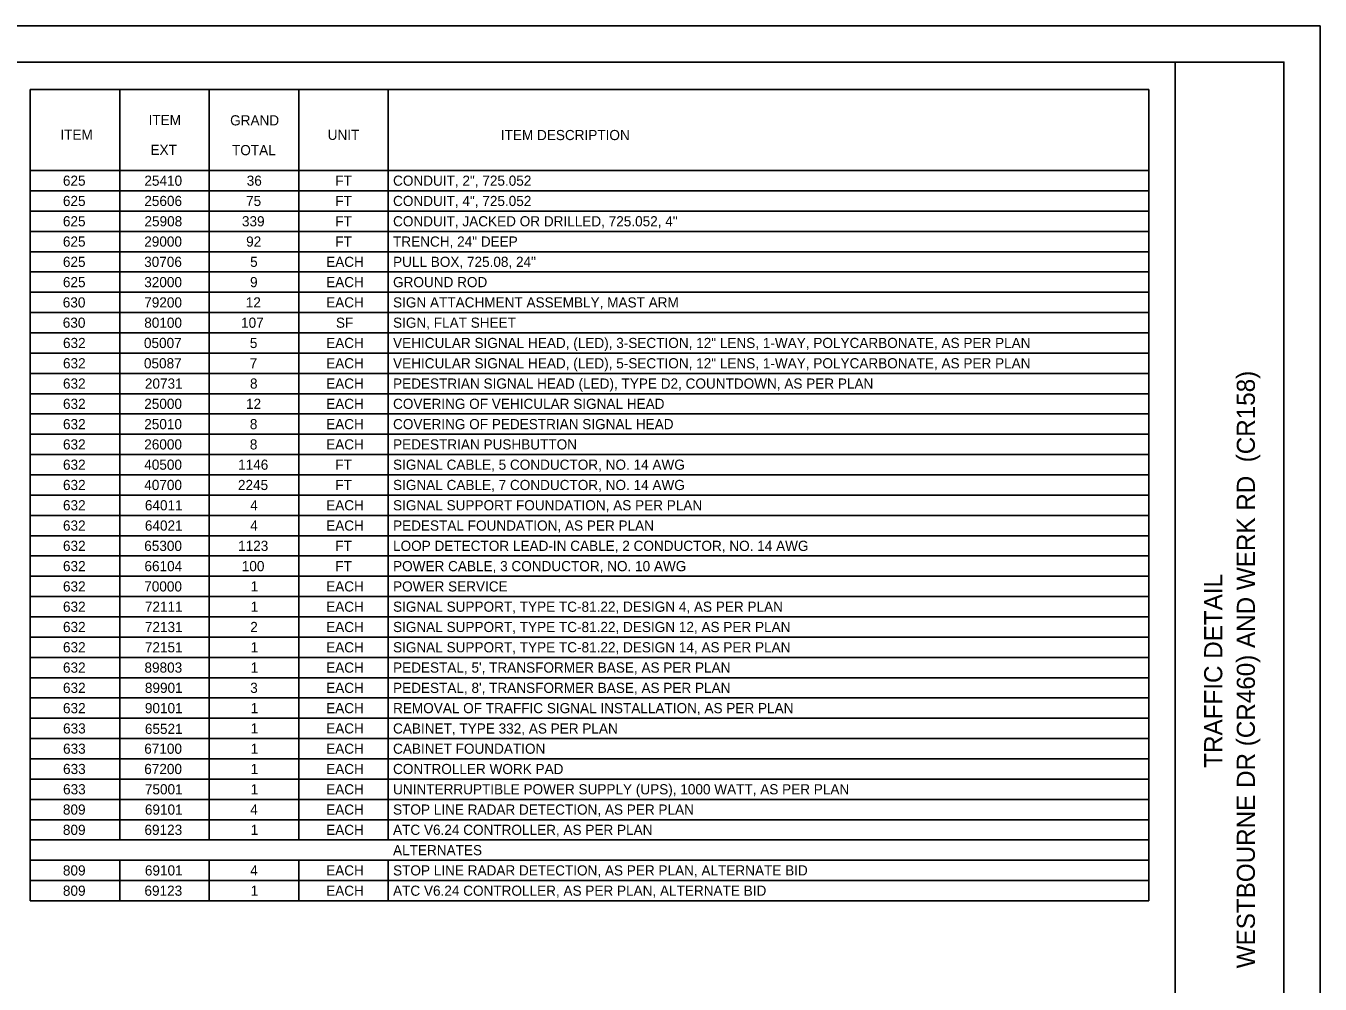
# Model space of a CAD drawing. Extents: x 5.5 to 39.5, y -2.1 to 19.9.
# Drawn here: x 21.69 to 39.55, y 6.69 to 19.91 of the extents above; entities that cross this region are included whole.
import ezdxf

# ---------------------------------------------------------------- set-up
doc = ezdxf.new("R2010")
doc.units = 0
for name, color, linetype in [('DR_X_Cells', 7, 'Continuous'), ('SC_Scratch1', 7, 'Continuous'), ('UT_P_Water_Cells', 7, 'Continuous'), ('UT_X_Misc_Cells', 7, 'Continuous')]:
    doc.layers.add(name, color=color, linetype=linetype)

msp = doc.modelspace()

# ---------------------------------------------------------------- linework, layer by layer
at = {"layer": 'DR_X_Cells'}
msp.add_lwpolyline([(5.548, -2.088), (39.548, -2.088), (39.548, 19.912), (5.548, 19.912)], close=True, dxfattribs=at)
at = {"layer": 'SC_Scratch1'}
msp.add_line((37.548, -1.588), (37.548, 19.412), dxfattribs=at)
msp.add_lwpolyline([(7.048, 19.412), (39.048, 19.412), (39.048, -1.588), (7.048, -1.588)], close=True, dxfattribs=at)
at = {"layer": 'UT_P_Water_Cells'}
for p, q in [((21.75, 19.035), (21.75, 7.835)), ((21.75, 19.035), (37.183, 19.035)), ((22.985, 19.035), (22.985, 8.675)), ((24.22, 19.035), (24.22, 8.675)), ((25.456, 19.035), (25.456, 8.675)), ((26.691, 19.035), (26.691, 8.675)), ((37.183, 19.035), (37.183, 7.835)), ((21.75, 17.915), (37.183, 17.915)), ((21.75, 17.635), (37.183, 17.635)), ((21.75, 17.355), (37.183, 17.355)), ((21.75, 17.075), (37.183, 17.075)), ((21.75, 16.795), (37.183, 16.795)), ((21.75, 16.515), (37.183, 16.515)), ((21.75, 16.235), (37.183, 16.235)), ((21.75, 15.955), (37.183, 15.955)), ((21.75, 15.675), (37.183, 15.675)), ((21.75, 15.395), (37.183, 15.395)), ((21.75, 15.115), (37.183, 15.115)), ((21.75, 14.835), (37.183, 14.835)), ((21.75, 14.555), (37.183, 14.555)), ((21.75, 14.275), (37.183, 14.275)), ((21.75, 13.995), (37.183, 13.995)), ((21.75, 13.715), (37.183, 13.715)), ((21.75, 13.435), (37.183, 13.435)), ((21.75, 13.155), (37.183, 13.155)), ((21.75, 12.875), (37.183, 12.875)), ((21.75, 12.595), (37.183, 12.595)), ((21.75, 12.315), (37.183, 12.315)), ((21.75, 12.035), (37.183, 12.035)), ((21.75, 11.755), (37.183, 11.755)), ((21.75, 11.475), (37.183, 11.475)), ((21.75, 11.475), (37.183, 11.475)), ((21.75, 11.195), (37.183, 11.195)), ((21.75, 10.915), (37.183, 10.915)), ((21.75, 10.635), (37.183, 10.635)), ((21.75, 10.355), (37.183, 10.355)), ((21.75, 10.075), (37.183, 10.075)), ((21.75, 9.795), (37.183, 9.795)), ((21.75, 9.515), (37.183, 9.515)), ((21.75, 9.235), (37.183, 9.235)), ((21.75, 8.955), (37.183, 8.955)), ((21.75, 8.675), (37.183, 8.675)), ((21.75, 8.395), (37.183, 8.395)), ((22.985, 8.395), (22.985, 7.835)), ((24.22, 8.395), (24.22, 7.835)), ((25.456, 8.395), (25.456, 7.835)), ((26.691, 8.395), (26.691, 7.835)), ((21.75, 8.115), (37.183, 8.115)), ((21.75, 7.835), (37.183, 7.835))]:
    msp.add_line(p, q, dxfattribs=at)

# ---------------------------------------------------------------- texts
for s, p in [('WESTBOURNE DR (CR460) AND WERK RD  (CR158)', (38.648, 6.904)), ('TRAFFIC DETAIL', (38.198, 9.672))]:
    msp.add_text(s, height=0.25, rotation=90, dxfattribs=at).set_placement(p)
at = {"layer": 'UT_X_Misc_Cells'}
for s, p in [('ITEM', (23.384, 18.542)), ('GRAND', (24.509, 18.538)), ('ITEM', (22.167, 18.339)), ('UNIT', (25.855, 18.338)), ('ITEM DESCRIPTION', (28.244, 18.335)), ('EXT', (23.41, 18.131)), ('TOTAL', (24.535, 18.127)), ('625', (22.202, 17.705)), ('25410', (23.326, 17.705)), ('36', (24.738, 17.705)), ('FT', (25.961, 17.705)), ('CONDUIT, 2", 725.052 ', (26.757, 17.705)), ('625', (22.202, 17.425)), ('25606', (23.325, 17.425)), ('75', (24.729, 17.425)), ('FT', (25.961, 17.425)), ('CONDUIT, 4", 725.052 ', (26.757, 17.425)), ('625', (22.202, 17.145)), ('25908', (23.327, 17.145)), ('339', (24.672, 17.145)), ('FT', (25.961, 17.145)), ('CONDUIT, JACKED OR DRILLED, 725.052, 4"', (26.757, 17.145)), ('625', (22.202, 16.865)), ('29000', (23.324, 16.865)), ('92', (24.73, 16.865)), ('FT', (25.961, 16.865)), ('TRENCH, 24" DEEP ', (26.757, 16.865)), ('625', (22.202, 16.585)), ('30706', (23.323, 16.585)), ('5', (24.785, 16.585)), ('EACH', (25.834, 16.585)), ('PULL BOX, 725.08, 24" ', (26.757, 16.585)), ('625', (22.202, 16.305)), ('32000', (23.324, 16.305)), ('9', (24.784, 16.305)), ('EACH', (25.834, 16.305)), ('GROUND ROD ', (26.757, 16.305)), ('630', (22.2, 16.025)), ('79200', (23.324, 16.025)), ('12', (24.725, 16.025)), ('EACH', (25.834, 16.025)), ('SIGN ATTACHMENT ASSEMBLY, MAST ARM', (26.757, 16.025)), ('630', (22.2, 15.745)), ('80100', (23.324, 15.745)), ('107', (24.66, 15.745)), ('SF', (25.969, 15.745)), ('SIGN, FLAT SHEET ', (26.757, 15.745)), ('632', (22.203, 15.465)), ('05007', (23.32, 15.465)), ('5', (24.781, 15.465)), ('EACH', (25.834, 15.465)), ('VEHICULAR SIGNAL HEAD, (LED), 3-SECTION, 12" LENS, 1-WAY, POLYCARBONATE, AS PER PLAN', (26.757, 15.465)), ('632', (22.203, 15.185)), ('05087', (23.32, 15.185)), ('7', (24.779, 15.185)), ('EACH', (25.834, 15.185)), ('VEHICULAR SIGNAL HEAD, (LED), 5-SECTION, 12" LENS, 1-WAY, POLYCARBONATE, AS PER PLAN', (26.757, 15.185)), ('632', (22.203, 14.905)), ('20731', (23.333, 14.905)), ('8', (24.783, 14.905)), ('EACH', (25.834, 14.905)), ('PEDESTRIAN SIGNAL HEAD (LED), TYPE D2, COUNTDOWN, AS PER PLAN', (26.757, 14.905)), ('632', (22.203, 14.625)), ('25000', (23.324, 14.625)), ('12', (24.728, 14.625)), ('EACH', (25.834, 14.625)), ('COVERING OF VEHICULAR SIGNAL HEAD ', (26.757, 14.625)), ('632', (22.203, 14.345)), ('25010', (23.324, 14.345)), ('8', (24.781, 14.345)), ('EACH', (25.834, 14.345)), ('COVERING OF PEDESTRIAN SIGNAL HEAD ', (26.757, 14.345)), ('632', (22.203, 14.065)), ('26000', (23.324, 14.065)), ('8', (24.781, 14.065)), ('EACH', (25.834, 14.065)), ('PEDESTRIAN PUSHBUTTON', (26.757, 14.065)), ('632', (22.203, 13.785)), ('40500', (23.324, 13.785)), ('1146', (24.619, 13.785)), ('FT', (25.961, 13.785)), ('SIGNAL CABLE, 5 CONDUCTOR, NO. 14 AWG ', (26.757, 13.785)), ('632', (22.203, 13.505)), ('40700', (23.324, 13.505)), ('2245', (24.617, 13.505)), ('FT', (25.961, 13.505)), ('SIGNAL CABLE, 7 CONDUCTOR, NO. 14 AWG ', (26.757, 13.505)), ('632', (22.203, 13.225)), ('64011', (23.333, 13.225)), ('4', (24.786, 13.225)), ('EACH', (25.834, 13.225)), ('SIGNAL SUPPORT FOUNDATION, AS PER PLAN ', (26.757, 13.225)), ('632', (22.203, 12.945)), ('64021', (23.333, 12.945)), ('4', (24.786, 12.945)), ('EACH', (25.834, 12.945)), ('PEDESTAL FOUNDATION, AS PER PLAN', (26.757, 12.945)), ('632', (22.203, 12.665)), ('65300', (23.324, 12.665)), ('1123', (24.619, 12.665)), ('FT', (25.961, 12.665)), ('LOOP DETECTOR LEAD-IN CABLE, 2 CONDUCTOR, NO. 14 AWG', (26.757, 12.665)), ('632', (22.203, 12.385)), ('66104', (23.327, 12.385)), ('100', (24.67, 12.385)), ('FT', (25.961, 12.385)), ('POWER CABLE, 3 CONDUCTOR, NO. 10 AWG ', (26.757, 12.385)), ('632', (22.203, 12.105)), ('70000', (23.324, 12.105)), ('1', (24.792, 12.105)), ('EACH', (25.834, 12.105)), ('POWER SERVICE', (26.757, 12.105)), ('632', (22.203, 11.825)), ('72111', (23.333, 11.825)), ('1', (24.792, 11.825)), ('EACH', (25.834, 11.825)), ('SIGNAL SUPPORT, TYPE TC-81.22, DESIGN 4, AS PER PLAN', (26.757, 11.825)), ('632', (22.203, 11.545)), ('72131', (23.333, 11.545)), ('2', (24.786, 11.545)), ('EACH', (25.834, 11.545)), ('SIGNAL SUPPORT, TYPE TC-81.22, DESIGN 12, AS PER PLAN', (26.757, 11.545)), ('632', (22.203, 11.265)), ('72151', (23.333, 11.265)), ('1', (24.792, 11.265)), ('EACH', (25.834, 11.265)), ('SIGNAL SUPPORT, TYPE TC-81.22, DESIGN 14, AS PER PLAN', (26.757, 11.265)), ('632', (22.203, 10.985)), ('89803', (23.327, 10.985)), ('1', (24.792, 10.985)), ('EACH', (25.834, 10.985)), ("PEDESTAL, 5', TRANSFORMER BASE, AS PER PLAN", (26.757, 10.985)), ('632', (22.203, 10.705)), ('89901', (23.333, 10.705)), ('3', (24.786, 10.705)), ('EACH', (25.834, 10.705)), ("PEDESTAL, 8', TRANSFORMER BASE, AS PER PLAN", (26.757, 10.705)), ('632', (22.203, 10.425)), ('90101', (23.333, 10.425)), ('1', (24.792, 10.425)), ('EACH', (25.834, 10.425)), ('REMOVAL OF TRAFFIC SIGNAL INSTALLATION, AS PER PLAN', (26.757, 10.425)), ('633', (22.204, 10.145)), ('65521', (23.333, 10.139)), ('1', (24.792, 10.145)), ('EACH', (25.834, 10.145)), ('CABINET, TYPE 332, AS PER PLAN', (26.757, 10.144)), ('633', (22.204, 9.865)), ('67100', (23.324, 9.865)), ('1', (24.792, 9.865)), ('EACH', (25.834, 9.865)), ('CABINET FOUNDATION', (26.757, 9.865)), ('633', (22.204, 9.585)), ('67200', (23.324, 9.585)), ('1', (24.792, 9.585)), ('EACH', (25.834, 9.585)), ('CONTROLLER WORK PAD ', (26.757, 9.585)), ('633', (22.204, 9.305)), ('75001', (23.333, 9.305)), ('1', (24.792, 9.305)), ('EACH', (25.834, 9.305)), ('UNINTERRUPTIBLE POWER SUPPLY (UPS), 1000 WATT, AS PER PLAN', (26.757, 9.305)), ('809', (22.202, 9.025)), ('69101', (23.333, 9.025)), ('4', (24.786, 9.025)), ('EACH', (25.834, 9.025)), ('STOP LINE RADAR DETECTION, AS PER PLAN ', (26.757, 9.025)), ('809', (22.202, 8.745)), ('69123', (23.327, 8.745)), ('1', (24.792, 8.745)), ('EACH', (25.834, 8.745)), ('ATC V6.24 CONTROLLER, AS PER PLAN ', (26.757, 8.745)), ('ALTERNATES', (26.757, 8.465)), ('809', (22.202, 8.185)), ('69101', (23.333, 8.185)), ('4', (24.786, 8.185)), ('EACH', (25.834, 8.185)), ('STOP LINE RADAR DETECTION, AS PER PLAN, ALTERNATE BID', (26.757, 8.185)), ('809', (22.202, 7.905)), ('69123', (23.327, 7.905)), ('1', (24.792, 7.905)), ('EACH', (25.834, 7.905)), ('ATC V6.24 CONTROLLER, AS PER PLAN, ALTERNATE BID', (26.757, 7.905))]:
    msp.add_text(s, height=0.14, dxfattribs=at).set_placement(p)

doc.saveas('drawing.dxf')
